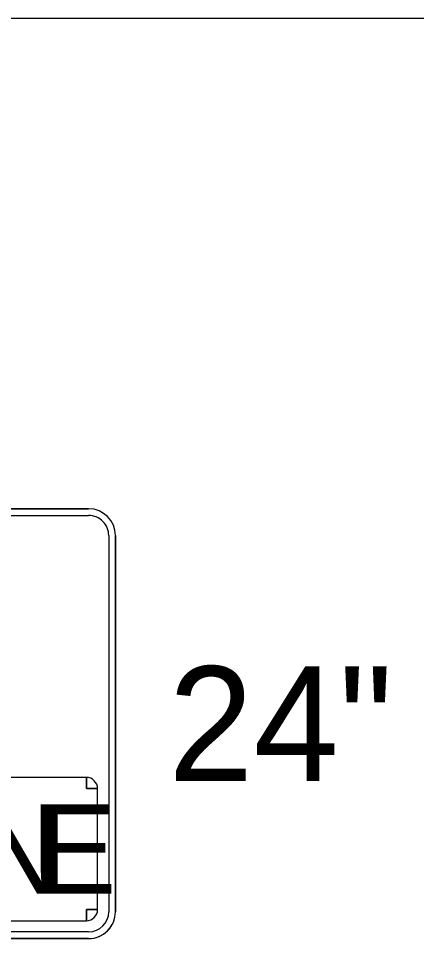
# Model space of a CAD drawing. Extents: x 99958 to 100176, y 99935 to 100011.
# Drawn here: x 100026.671 to 100026.922, y 99973.998 to 99974.576 of the extents above; entities that cross this region are included whole.
import ezdxf

# ---------------------------------------------------------------- set-up
doc = ezdxf.new("R2010")
doc.units = 0
doc.layers.add('TR_SN_ConstructionSigns', color=7, linetype='Continuous')
doc.layers.add('TR_WZ_WorkZoneDetails', color=7, linetype='Continuous')

msp = doc.modelspace()

# ---------------------------------------------------------------- linework, layer by layer
at = {"layer": 'TR_SN_ConstructionSigns'}
for p, q in [((100026.71544, 99974.26773), (100026.41169, 99974.26773)), ((100026.71544, 99974.26773), (100026.41169, 99974.26773)), ((100026.41169, 99974.26773), (100026.71544, 99974.26773)), ((100026.41169, 99974.26351), (100026.71544, 99974.26351)), ((100026.7281, 99974.25085), (100026.7281, 99974.0146)), ((100026.73232, 99974.0146), (100026.73232, 99974.25085)), ((100026.73232, 99974.0146), (100026.73232, 99974.25085)), ((100026.73232, 99974.25085), (100026.73232, 99974.0146)), ((100026.71404, 99974.09898), (100026.4131, 99974.09898)), ((100026.71404, 99974.09898), (100026.71404, 99974.09195)), ((100026.71404, 99974.09195), (100026.71404, 99974.09898)), ((100026.71404, 99974.09195), (100026.72107, 99974.09195)), ((100026.72107, 99974.09195), (100026.71404, 99974.09195)), ((100026.72107, 99974.01601), (100026.72107, 99974.09195)), ((100026.72107, 99974.01601), (100026.71404, 99974.01601)), ((100026.71404, 99974.01601), (100026.71404, 99974.00898)), ((100026.71404, 99974.00898), (100026.71404, 99974.01601)), ((100026.71404, 99974.01601), (100026.72107, 99974.01601)), ((100026.4131, 99974.00898), (100026.71404, 99974.00898)), ((100026.71544, 99974.00195), (100026.41169, 99974.00195)), ((100026.41169, 99973.99773), (100026.71544, 99973.99773)), ((100026.41169, 99973.99773), (100026.71544, 99973.99773)), ((100026.71544, 99973.99773), (100026.41169, 99973.99773))]:
    msp.add_line(p, q, dxfattribs=at)
for centre, radius, start, end in [((100026.71544, 99974.25085), 0.01688, 0.00001, 90.00001), ((100026.71544, 99974.25085), 0.01688, 0.00001, 90.00001), ((100026.71544, 99974.25085), 0.01688, 0, 90), ((100026.71544, 99974.25085), 0.01266, 0, 90.00001), ((100026.71404, 99974.09195), 0.00703, 0, 90), ((100026.71404, 99974.01601), 0.00703, 270.00001, 0.00001), ((100026.71544, 99974.0146), 0.01688, 270, 0.00001), ((100026.71544, 99974.0146), 0.01688, 270, 0.00001), ((100026.71544, 99974.0146), 0.01266, 270.00001, 0), ((100026.71544, 99974.0146), 0.01688, 270, 0)]:
    msp.add_arc(centre, radius, start, end, dxfattribs=at)
at = {"layer": 'TR_WZ_WorkZoneDetails'}
msp.add_line((100029.46988, 99974.57573), (100026.6573, 99974.57573), dxfattribs=at)

# ---------------------------------------------------------------- texts
at = {"layer": 'TR_SN_ConstructionSigns'}
msp.add_text('24"', height=0.072, rotation=360, dxfattribs=at).set_placement((100026.76556, 99974.09673))
for s, p in [('N', (100026.64336, 99974.02585)), ('E', (100026.6828, 99974.02585))]:
    msp.add_text(s, height=0.05625, dxfattribs=at).set_placement(p)

doc.saveas('drawing.dxf')
